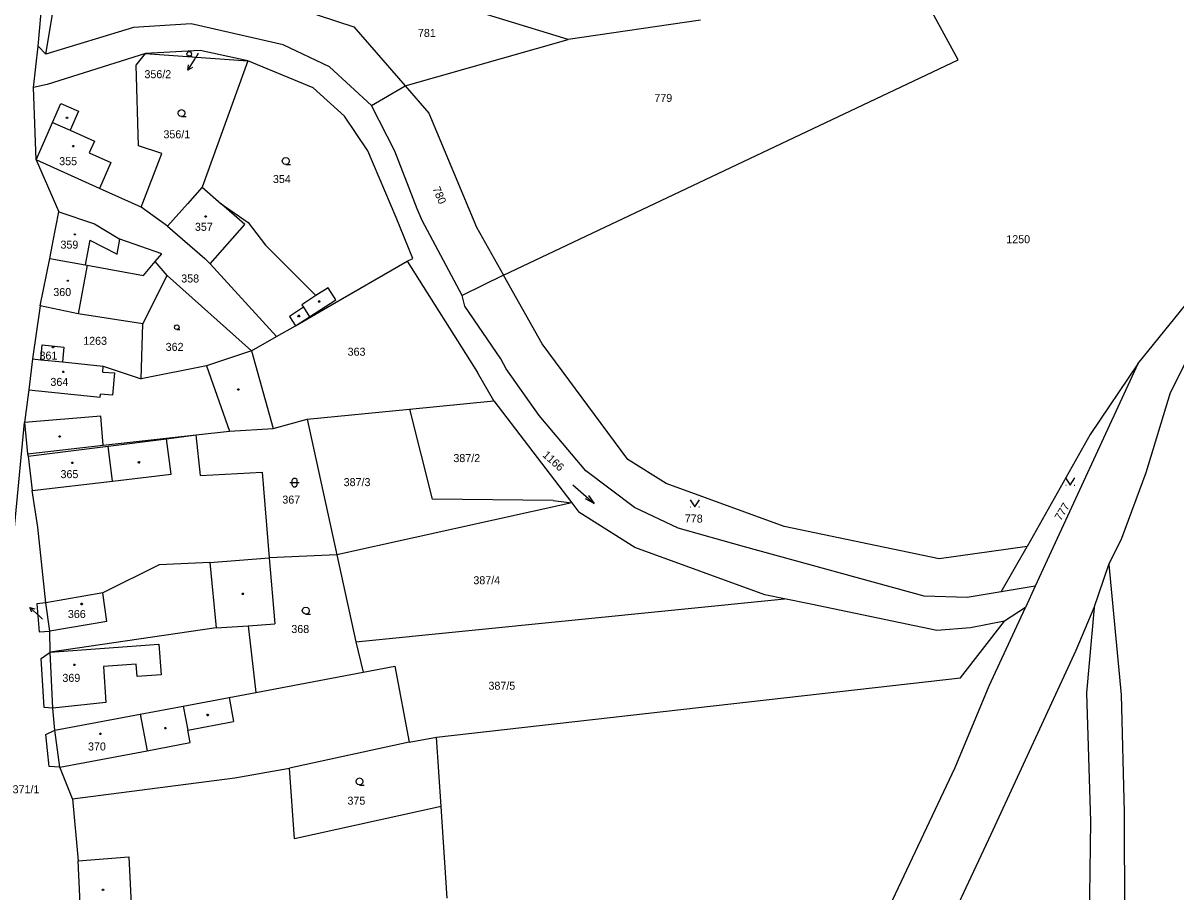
# Model space of a CAD drawing. Extents: x -812394 to -807601, y -1013097 to -1009266.
# Drawn here: x -811005.4 to -810760.5, y -1011411.9 to -1011227.4 of the extents above; entities that cross this region are included whole.
import ezdxf

# ---------------------------------------------------------------- set-up
doc = ezdxf.new("R2010")
doc.units = 0
for name, color, linetype in [('Default', 7, 'Continuous'), ('KN_HRANICE', 7, 'Continuous'), ('KN_KULTURY', 7, 'Continuous'), ('KN_PARCELY', 7, 'Continuous'), ('KN_SLUCKY', 7, 'Continuous')]:
    doc.layers.add(name, color=color, linetype=linetype)

# ---------------------------------------------------------------- blocks, each defined once
blk = doc.blocks.new('10292')
at = {"layer": 'Default'}
blk.add_line((0, 3), (0, 0), dxfattribs=at)
blk.add_lwpolyline([(-0.5, 2), (0, 3), (0.5, 2)], dxfattribs=at)
blk = doc.blocks.new('304')
at = {"layer": 'Default'}
blk.add_lwpolyline([(0, 0), (-0.38, 0.1), (-0.65, 0.37), (-0.75, 0.74), (-0.65, 1.11), (-0.38, 1.38), (-0.01, 1.48), (0.36, 1.38), (0.63, 1.11), (0.73, 0.73), (0.63, 0.35), (0.36, 0.08), (-0.02, -0.02), (0.98, -0.02)], dxfattribs=at)
blk = doc.blocks.new('314')
at = {"layer": 'Default'}
for p, q in [((-0.95, 0), (-0.85, 0)), ((0.85, 0), (0.95, 0))]:
    blk.add_line(p, q, dxfattribs=at)
blk.add_lwpolyline([(-1, 1.5), (0, 0), (1, 1.5)], dxfattribs=at)
blk = doc.blocks.new('316')
at = {"layer": 'Default'}
for points in [[(-1, 1), (0.27, 1), (1, 1)], [(-0.5, 1.5), (-0.4, 1.79), (-0.15, 1.97), (0.16, 1.97), (0.41, 1.79), (0.51, 1.5), (0.51, 0.5), (0.41, 0.21), (0.16, 0.03), (-0.15, 0.03), (-0.4, 0.21), (-0.5, 0.5), (-0.5, 1.5)]]:
    blk.add_lwpolyline(points, dxfattribs=at)
blk = doc.blocks.new('802')
at = {"layer": 'Default'}
blk.add_line((-3, 0), (3, 0), dxfattribs=at)
blk.add_lwpolyline([(1, 0.5), (3, 0), (1, -0.5)], dxfattribs=at)
blk = doc.blocks.new('402')
at = {"layer": 'Default'}
blk.add_lwpolyline([(0.09, 0.15), (0.18, 0), (0.09, -0.15), (-0.09, -0.15), (-0.18, 0), (-0.09, 0.15), (0.09, 0.15)], dxfattribs=at)

msp = doc.modelspace()

# ---------------------------------------------------------------- linework, layer by layer
at = {"layer": 'KN_HRANICE'}
for p, q in [((-810806.75, -1011235.18), (-810824.69, -1011202.01)), ((-811002.17, -1011232.3), (-810999.64, -1011204.43)), ((-810889.59, -1011230.84), (-810947.19, -1011213.16)), ((-810965.7, -1011218.1), (-810935.11, -1011228.19)), ((-810861.45, -1011226.78), (-810889.59, -1011230.84)), ((-810981.89, -1011228.33), (-811000.55, -1011233.96)), ((-810969.64, -1011227.53), (-810981.89, -1011228.33)), ((-810950.13, -1011231.95), (-810969.64, -1011227.53)), ((-810935.11, -1011228.19), (-810924.23, -1011240.7)), ((-811003.16, -1011241.04), (-811002.17, -1011232.3)), ((-811000.55, -1011233.96), (-811002.17, -1011232.3)), ((-810940.26, -1011236.62), (-810950.13, -1011231.95)), ((-810924.23, -1011240.7), (-810889.59, -1011230.84)), ((-810979.36, -1011233.79), (-811000.25, -1011240.41)), ((-810981.35, -1011236.28), (-810979.36, -1011233.79)), ((-810967.75, -1011233.22), (-810979.36, -1011233.79)), ((-810979.36, -1011233.79), (-810957.6, -1011235.39)), ((-810957.6, -1011235.39), (-810967.75, -1011233.22)), ((-810980.83, -1011253.42), (-810981.35, -1011236.28)), ((-810957.6, -1011235.39), (-810967.33, -1011262.22)), ((-810943.72, -1011241.14), (-810957.6, -1011235.39)), ((-810931.35, -1011244.85), (-810940.26, -1011236.62)), ((-810903.34, -1011280.87), (-810806.75, -1011235.18)), ((-811000.25, -1011240.41), (-811003.16, -1011241.04)), ((-811002.62, -1011256.43), (-811003.16, -1011241.04)), ((-810937.08, -1011247.12), (-810943.72, -1011241.14)), ((-810931.35, -1011244.85), (-810924.23, -1011240.7)), ((-810924.23, -1011240.7), (-810919.19, -1011246.5)), ((-810926.38, -1011254.58), (-810931.35, -1011244.85)), ((-810919.19, -1011246.5), (-810909.08, -1011270.71)), ((-810932.1, -1011254.51), (-810937.08, -1011247.12)), ((-810975.86, -1011255.03), (-810980.83, -1011253.42)), ((-810989.17, -1011262.49), (-811002.62, -1011256.43)), ((-811002.62, -1011256.43), (-810997.78, -1011267.47)), ((-810980.3, -1011266.48), (-810975.86, -1011255.03)), ((-810926.1, -1011268.68), (-810932.1, -1011254.51)), ((-810921.65, -1011266.8), (-810926.38, -1011254.58)), ((-810980.3, -1011266.48), (-810989.17, -1011262.49)), ((-810967.33, -1011262.22), (-810970.46, -1011265.77)), ((-810967.33, -1011262.22), (-810963.3, -1011265.77)), ((-810974.72, -1011270.51), (-810980.3, -1011266.48)), ((-810970.46, -1011265.77), (-810974.72, -1011270.51)), ((-810963.3, -1011265.77), (-810957.54, -1011269.71)), ((-810999.06, -1011273.96), (-810997.78, -1011267.47)), ((-810997.78, -1011267.47), (-810990.19, -1011269.98)), ((-810922.58, -1011277.32), (-810926.1, -1011268.68)), ((-810920.56, -1011269.26), (-810921.65, -1011266.8)), ((-810990.19, -1011269.98), (-810984.79, -1011273.26)), ((-810974.72, -1011270.51), (-810966.78, -1011277.34)), ((-810957.54, -1011269.71), (-810953.85, -1011274.53)), ((-810912.07, -1011285.18), (-810920.56, -1011269.26)), ((-810909.08, -1011270.71), (-810903.34, -1011280.87)), ((-810999.13, -1011274.36), (-810999.06, -1011273.96)), ((-810975.9, -1011276.34), (-810984.79, -1011273.26)), ((-810999.71, -1011277.35), (-810999.13, -1011274.36)), ((-810977.29, -1011278), (-810975.9, -1011276.34)), ((-810953.85, -1011274.53), (-810943.16, -1011285.24)), ((-811001.73, -1011287.39), (-810999.71, -1011277.35)), ((-810999.71, -1011277.35), (-810992.18, -1011278.71)), ((-810992.18, -1011278.71), (-810991.74, -1011278.8)), ((-810991.74, -1011278.8), (-810979.77, -1011280.96)), ((-810979.77, -1011280.96), (-810977.29, -1011278)), ((-810974.77, -1011280.94), (-810977.29, -1011278)), ((-810965.64, -1011278.49), (-810966.78, -1011277.34)), ((-810951.55, -1011293.91), (-810965.64, -1011278.49)), ((-810923.78, -1011277.95), (-810922.58, -1011277.32)), ((-810923.78, -1011277.95), (-810908.87, -1011301.53)), ((-810979.92, -1011291.21), (-810974.77, -1011280.94)), ((-810956.84, -1011296.95), (-810974.77, -1011280.94)), ((-810903.34, -1011280.87), (-810912.07, -1011285.18)), ((-810895.09, -1011295.44), (-810903.34, -1011280.87)), ((-810768.55, -1011299.75), (-810752.37, -1011279.68)), ((-810940.55, -1011283.55), (-810943.16, -1011285.24)), ((-810938.93, -1011286.14), (-810940.55, -1011283.55)), ((-810944.54, -1011289.74), (-810938.93, -1011286.14)), ((-810911.54, -1011287.46), (-810912.07, -1011285.18)), ((-811001.73, -1011287.39), (-811003.39, -1011298.68)), ((-810993.66, -1011289.11), (-811001.73, -1011287.39)), ((-810903.9, -1011298.68), (-810911.54, -1011287.46)), ((-810979.92, -1011291.21), (-810993.66, -1011289.11)), ((-810947.5, -1011291.64), (-810944.54, -1011289.74)), ((-810980.3, -1011302.9), (-810979.92, -1011291.21)), ((-810951.55, -1011293.91), (-810947.5, -1011291.64)), ((-810956.84, -1011296.95), (-810951.55, -1011293.91)), ((-810876.93, -1011320.01), (-810895.09, -1011295.44)), ((-810956.84, -1011296.95), (-810966.4, -1011300.17)), ((-810956.84, -1011296.95), (-810952.23, -1011313.45)), ((-811003.39, -1011298.68), (-811004.13, -1011305.26)), ((-811003.39, -1011298.68), (-811001.63, -1011298.87)), ((-811001.63, -1011298.87), (-810997.01, -1011299.33)), ((-810997.01, -1011299.33), (-810988.33, -1011300.21)), ((-810988.33, -1011300.21), (-810980.3, -1011302.9)), ((-810966.4, -1011300.17), (-810980.3, -1011302.9)), ((-810902.75, -1011300.77), (-810903.9, -1011298.68)), ((-810895.77, -1011310.66), (-810902.75, -1011300.77)), ((-810768.55, -1011299.75), (-810790.34, -1011346.91)), ((-810768.55, -1011299.75), (-810778.68, -1011314.73)), ((-810905.37, -1011307.57), (-810908.87, -1011301.53)), ((-811004.22, -1011305.74), (-811005.05, -1011312.16)), ((-811004.13, -1011305.26), (-811004.22, -1011305.74)), ((-810923.25, -1011309.32), (-810905.37, -1011307.57)), ((-810905.37, -1011307.57), (-810888.79, -1011329.27)), ((-810945.05, -1011311.46), (-810923.25, -1011309.32)), ((-810923.25, -1011309.32), (-810918.46, -1011328.49)), ((-810885.8, -1011322.45), (-810895.77, -1011310.66)), ((-811011.64, -1011380.82), (-811005.05, -1011312.16)), ((-811005.05, -1011312.16), (-811004.45, -1011318.84)), ((-810952.23, -1011313.45), (-810945.05, -1011311.46)), ((-810945.05, -1011311.46), (-810938.72, -1011340.26)), ((-810988.35, -1011317), (-810968.58, -1011314.81)), ((-810968.58, -1011314.81), (-810961.52, -1011314.03)), ((-810967.67, -1011323.41), (-810968.58, -1011314.81)), ((-810961.52, -1011314.03), (-810952.23, -1011313.45)), ((-810778.68, -1011314.73), (-810792.06, -1011338.51)), ((-811004.45, -1011318.84), (-810988.35, -1011317)), ((-811004.45, -1011318.84), (-811004.32, -1011319.34)), ((-811004.32, -1011319.34), (-811003.44, -1011326.63)), ((-810868.75, -1011325.15), (-810876.93, -1011320.01)), ((-810967.67, -1011323.41), (-810954.58, -1011322.7)), ((-810954.58, -1011322.7), (-810953.07, -1011340.89)), ((-810875.48, -1011330.25), (-810885.8, -1011322.45)), ((-810843.66, -1011334.29), (-810868.75, -1011325.15)), ((-811002.26, -1011334.39), (-811003.44, -1011326.63)), ((-810888.79, -1011329.27), (-810938.72, -1011340.26)), ((-810892.77, -1011328.76), (-810918.46, -1011328.49)), ((-810892.77, -1011328.76), (-810888.79, -1011329.27)), ((-810888.79, -1011329.27), (-810887.31, -1011331.21)), ((-810866.23, -1011334.63), (-810875.48, -1011330.25)), ((-810875.38, -1011338.7), (-810887.31, -1011331.21)), ((-811000.52, -1011350.48), (-811002.26, -1011334.39)), ((-810852.14, -1011338.55), (-810866.23, -1011334.63)), ((-810810.76, -1011341.14), (-810843.66, -1011334.29)), ((-810847.78, -1011348.75), (-810875.38, -1011338.7)), ((-810813.95, -1011349.06), (-810852.14, -1011338.55)), ((-810792.06, -1011338.51), (-810810.76, -1011341.14)), ((-810797.6, -1011348.14), (-810792.06, -1011338.51)), ((-810976.43, -1011342.38), (-810988.41, -1011348.38)), ((-810965.69, -1011341.89), (-810976.43, -1011342.38)), ((-810965.69, -1011341.89), (-810953.07, -1011340.89)), ((-810938.72, -1011340.26), (-810953.07, -1011340.89)), ((-810953.07, -1011340.89), (-810951.91, -1011354.96)), ((-810938.72, -1011340.26), (-810934.65, -1011358.77)), ((-810777.84, -1011351.43), (-810774.7, -1011342.36)), ((-810774.7, -1011342.36), (-810772.09, -1011370.03)), ((-810790.34, -1011346.91), (-810797.6, -1011348.14)), ((-810790.34, -1011346.91), (-810792.45, -1011351.48)), ((-810988.41, -1011348.38), (-811000.52, -1011350.48)), ((-810934.65, -1011358.77), (-810843.62, -1011349.61)), ((-810843.62, -1011349.61), (-810847.78, -1011348.75)), ((-810838.01, -1011350.78), (-810843.62, -1011349.61)), ((-810804.84, -1011349.37), (-810813.95, -1011349.06)), ((-810797.6, -1011348.14), (-810804.84, -1011349.37)), ((-811000.52, -1011350.48), (-811002.43, -1011350.69)), ((-811002.43, -1011350.69), (-811001.96, -1011356.64)), ((-810999.69, -1011356.51), (-811000.52, -1011350.48)), ((-810811.26, -1011356.36), (-810838.01, -1011350.78)), ((-810800.11, -1011368.06), (-810792.45, -1011351.48)), ((-810792.45, -1011351.48), (-810796.89, -1011354.34)), ((-810806.21, -1011366.42), (-810796.89, -1011354.34)), ((-810796.89, -1011354.34), (-810804.09, -1011355.77)), ((-811001.96, -1011356.64), (-810999.69, -1011356.51)), ((-810999.65, -1011360.93), (-810999.69, -1011356.51)), ((-810964.33, -1011355.78), (-810999.65, -1011360.93)), ((-810964.33, -1011355.78), (-810957.53, -1011355.33)), ((-810957.53, -1011355.33), (-810951.91, -1011354.96)), ((-810957.53, -1011355.33), (-810955.9, -1011369.48)), ((-810804.09, -1011355.77), (-810811.26, -1011356.36)), ((-810934.65, -1011358.77), (-810933.12, -1011365.18)), ((-811001.56, -1011362.3), (-810999.65, -1011360.93)), ((-811000.89, -1011372.69), (-811001.56, -1011362.3)), ((-810933.12, -1011365.18), (-810926.42, -1011363.89)), ((-810926.42, -1011363.89), (-810923.32, -1011380.04)), ((-810955.9, -1011369.48), (-810933.12, -1011365.18)), ((-810917.53, -1011379.01), (-810806.21, -1011366.42)), ((-810961.6, -1011370.56), (-810955.9, -1011369.48)), ((-810807.37, -1011385.45), (-810800.11, -1011368.06)), ((-810971.34, -1011372.39), (-810961.6, -1011370.56)), ((-810772.09, -1011370.03), (-810771.46, -1011394.94)), ((-810999.02, -1011372.81), (-811000.89, -1011372.69)), ((-810998.61, -1011377.54), (-810999.02, -1011372.81)), ((-810998.61, -1011377.54), (-810980.47, -1011374.12)), ((-810980.47, -1011374.12), (-810971.34, -1011372.39)), ((-811000.53, -1011378.46), (-810998.61, -1011377.54)), ((-810999.85, -1011385.23), (-811000.53, -1011378.46)), ((-810923.32, -1011380.04), (-810917.53, -1011379.01)), ((-810916.55, -1011393.72), (-810917.53, -1011379.01)), ((-810923.32, -1011380.04), (-810948.75, -1011385.55)), ((-810997.58, -1011385.39), (-810999.85, -1011385.23)), ((-810994.85, -1011392.06), (-810997.58, -1011385.39)), ((-810960.37, -1011387.63), (-810948.75, -1011385.55)), ((-810947.72, -1011400.58), (-810948.75, -1011385.55)), ((-810835.54, -1011445.05), (-810807.37, -1011385.45)), ((-810994.85, -1011392.06), (-810960.37, -1011387.63)), ((-810994.85, -1011392.06), (-810993.69, -1011405.27)), ((-810916.55, -1011393.72), (-810947.72, -1011400.58)), ((-810915.25, -1011413.2), (-810916.55, -1011393.72)), ((-810771.46, -1011394.94), (-810771.36, -1011424.92)), ((-810992.93, -1011421.31), (-810993.69, -1011405.27))]:
    msp.add_line(p, q, dxfattribs=at)
for points in [[(-811000.55, -1011233.96), (-810996.85, -1011211.94), (-810995.36, -1011212.19)], [(-810947.5, -1011291.64), (-810940.71, -1011287.68), (-810923.78, -1011277.95)], [(-810774.7, -1011342.36), (-810771.98, -1011336.72), (-810766.82, -1011322.78), (-810761.61, -1011305.79), (-810758.06, -1011298.78), (-810747.85, -1011288.99), (-810732.24, -1011285.59), (-810715.58, -1011286.24), (-810702.36, -1011291.29), (-810686.79, -1011296.15)], [(-811001.63, -1011298.87), (-811001.31, -1011295.7), (-810996.71, -1011296.15), (-810997.01, -1011299.33)], [(-810817.11, -1011436.78), (-810799.71, -1011399.57), (-810781.64, -1011360.53), (-810777.84, -1011351.43)], [(-810777.84, -1011351.43), (-810779.49, -1011369.6), (-810778.58, -1011396.9), (-810779, -1011423.07), (-810780.56, -1011441.53), (-810782.41, -1011459.43)]]:
    msp.add_lwpolyline(points, dxfattribs=at)
at = {"layer": 'KN_PARCELY'}
for p, q in [((-810968.16, -1011233.85), (-810968.76, -1011234.82)), ((-811001.27, -1011353.91), (-811001.74, -1011353.47))]:
    msp.add_line(p, q, dxfattribs=at)
at = {"layer": 'KN_SLUCKY'}
for p, q in [((-810999.12, -1011248.48), (-810997.34, -1011244.43)), ((-810997.34, -1011244.43), (-810993.61, -1011246.08)), ((-810993.61, -1011246.08), (-810995.4, -1011250.12)), ((-811000.26, -1011251.07), (-810999.12, -1011248.48)), ((-810999.12, -1011248.48), (-810995.4, -1011250.12)), ((-811002.62, -1011256.43), (-811000.26, -1011251.07)), ((-810995.4, -1011250.12), (-810990.22, -1011252.41)), ((-810990.22, -1011252.41), (-810991.33, -1011254.91)), ((-810991.33, -1011254.91), (-810986.72, -1011256.95)), ((-810986.72, -1011256.95), (-810989.17, -1011262.49)), ((-810958.24, -1011270.15), (-810963.3, -1011265.77)), ((-810965.64, -1011278.49), (-810958.24, -1011270.15)), ((-810991.16, -1011273.46), (-810992.18, -1011278.71)), ((-810991.16, -1011273.46), (-810985.41, -1011276.45)), ((-810985.41, -1011276.45), (-810984.79, -1011273.26)), ((-810991.74, -1011278.8), (-810993.66, -1011289.11)), ((-810943.16, -1011285.24), (-810946.14, -1011287.17)), ((-810945.83, -1011287.68), (-810948.74, -1011289.66)), ((-810946.14, -1011287.17), (-810945.83, -1011287.68)), ((-810945.83, -1011287.68), (-810944.54, -1011289.74)), ((-810948.74, -1011289.66), (-810947.5, -1011291.64)), ((-810988.45, -1011301.47), (-810988.33, -1011300.21)), ((-810966.4, -1011300.17), (-810961.52, -1011314.03)), ((-811004.13, -1011305.26), (-810988.97, -1011306.82)), ((-810988.97, -1011306.82), (-810988.9, -1011306.14)), ((-810988.84, -1011310.82), (-811005.05, -1011312.16)), ((-810988.35, -1011317), (-810988.84, -1011310.82)), ((-810974.87, -1011315.67), (-810968.58, -1011314.81)), ((-811004.32, -1011319.34), (-810987.28, -1011317.22)), ((-810987.28, -1011317.22), (-810974.87, -1011315.67)), ((-810986.41, -1011324.63), (-810987.28, -1011317.22)), ((-810973.9, -1011323.16), (-810974.87, -1011315.67)), ((-811003.44, -1011326.63), (-810986.41, -1011324.63)), ((-810986.41, -1011324.63), (-810973.9, -1011323.16)), ((-810965.69, -1011341.89), (-810964.33, -1011355.78)), ((-810987.58, -1011354.41), (-810988.41, -1011348.38)), ((-810987.58, -1011354.41), (-810999.69, -1011356.51)), ((-810999.65, -1011360.93), (-810976.53, -1011359.27)), ((-810976.53, -1011359.27), (-810976.05, -1011365.75)), ((-810999.02, -1011372.81), (-810999.65, -1011360.93)), ((-810981.33, -1011363.48), (-810988.3, -1011364)), ((-810988.3, -1011364), (-810987.79, -1011371.62)), ((-810981.13, -1011366.12), (-810981.33, -1011363.48)), ((-810976.05, -1011365.75), (-810981.13, -1011366.12)), ((-810987.79, -1011371.62), (-810999.02, -1011372.81)), ((-810961.6, -1011370.56), (-810960.64, -1011375.67)), ((-810980.47, -1011374.12), (-810979.01, -1011381.89)), ((-810971.34, -1011372.39), (-810970.37, -1011377.51)), ((-810970.37, -1011377.51), (-810960.64, -1011375.67)), ((-810997.58, -1011385.39), (-810998.61, -1011377.54)), ((-810969.87, -1011380.16), (-810970.37, -1011377.51)), ((-810979.01, -1011381.89), (-810969.87, -1011380.16)), ((-810997.58, -1011385.39), (-810979.01, -1011381.89)), ((-810993.69, -1011405.27), (-810982.89, -1011404.38)), ((-810982.89, -1011404.38), (-810982.08, -1011420.69))]:
    msp.add_line(p, q, dxfattribs=at)
msp.add_lwpolyline([(-810988.45, -1011301.47), (-810985.92, -1011301.66), (-810986.34, -1011306.35), (-810988.9, -1011306.14)], dxfattribs=at)

# ---------------------------------------------------------------- block references
at = {"layer": 'KN_KULTURY', "xscale": 0.67, "yscale": 0.67}
for name, p in [('304', (-810970.08, -1011234.4)), ('402', (-810994.37, -1011272.23)), ('402', (-810995.85, -1011282.09)), ('304', (-810972.71, -1011292.44))]:
    msp.add_blockref(name, p, dxfattribs=at)
at = {"layer": 'KN_KULTURY'}
for name, p in [('304', (-810971.71, -1011247.21)), ('402', (-810996.06, -1011247.46)), ('402', (-810994.72, -1011253.52)), ('304', (-810949.56, -1011257.39)), ('402', (-810966.59, -1011268.43)), ('402', (-810942.47, -1011286.48)), ('402', (-810946.79, -1011289.56)), ('402', (-810999, -1011296.18)), ('402', (-810996.85, -1011301.42)), ('402', (-810959.65, -1011305.15)), ('402', (-810997.58, -1011315.14)), ('402', (-810980.77, -1011320.64)), ('402', (-810994.9, -1011320.73)), ('316', (-810947.7, -1011325.94)), ('314', (-810782.92, -1011325.46)), ('314', (-810862.65, -1011330.12)), ('402', (-810958.69, -1011348.58)), ('402', (-810992.92, -1011350.71)), ('304', (-810945.31, -1011352.87)), ('402', (-810994.46, -1011363.63)), ('402', (-810966.13, -1011374.29)), ('402', (-810988.94, -1011378.29)), ('402', (-810975.13, -1011377.06)), ('304', (-810933.89, -1011389.14)), ('402', (-810988.38, -1011411.41))]:
    msp.add_blockref(name, p, dxfattribs=at)
at = {"layer": 'KN_KULTURY', "rotation": -41.20628299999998}
msp.add_blockref('802', (-810886.31, -1011327.38), dxfattribs=at)
at = {"layer": 'KN_PARCELY'}
for p, rotation in [((-810968.76, -1011234.82), 148.224182), ((-811001.74, -1011353.47), 47.097131)]:
    msp.add_blockref('10292', p, dxfattribs=dict(at, rotation=rotation))

# ---------------------------------------------------------------- texts
for s, height, p in [('781', 1.7, (-810921.49, -1011230.31)), ('356/2', 0.1, (-810968.4, -1011233.85)), ('356/2', 1.7, (-810979.59, -1011239.07)), ('779', 1.7, (-810871.26, -1011244.11)), ('356/1', 1.7, (-810975.55, -1011251.83)), ('355', 1.7, (-810997.7, -1011257.54)), ('354', 1.7, (-810952.29, -1011261.33)), ('357', 1.7, (-810968.87, -1011271.48)), ('359', 1.7, (-810997.43, -1011275.26)), ('1250', 1.7, (-810796.5, -1011274.11)), ('358', 1.7, (-810971.77, -1011282.45)), ('360', 1.7, (-810998.95, -1011285.33)), ('1263', 1.7, (-810992.6, -1011295.68)), ('362', 1.7, (-810975.08, -1011296.97)), ('361', 1.7, (-811001.88, -1011298.82)), ('363', 1.7, (-810936.43, -1011298)), ('364', 1.7, (-810999.56, -1011304.41)), ('387/2', 1.7, (-810913.96, -1011320.59)), ('365', 1.7, (-810997.42, -1011323.99)), ('387/3', 1.7, (-810937.27, -1011325.69)), ('367', 1.7, (-810950.3, -1011329.4)), ('387/4', 1.7, (-810909.71, -1011346.52)), ('366', 1.7, (-810995.85, -1011353.69)), ('371/2', 0.1, (-811001.51, -1011353.91)), ('368', 1.7, (-810948.38, -1011356.88)), ('369', 1.7, (-810997.02, -1011367.25)), ('387/5', 1.7, (-810906.5, -1011368.92)), ('370', 1.7, (-810991.58, -1011381.82)), ('371/1', 1.7, (-811007.6, -1011390.91)), ('375', 1.7, (-810936.46, -1011393.33))]:
    msp.add_text(s, height=height, dxfattribs=at).set_placement(p)
for s, rotation, p in [('780', 293.125, (-810918.44, -1011262.49)), ('1166', 318.049, (-810895.15, -1011319.27)), ('777', 58.27, (-810784.93, -1011333.16)), ('778', 359.359, (-810864.8, -1011333.39))]:
    msp.add_text(s, height=1.7, rotation=rotation, dxfattribs=at).set_placement(p)

doc.saveas('drawing.dxf')
